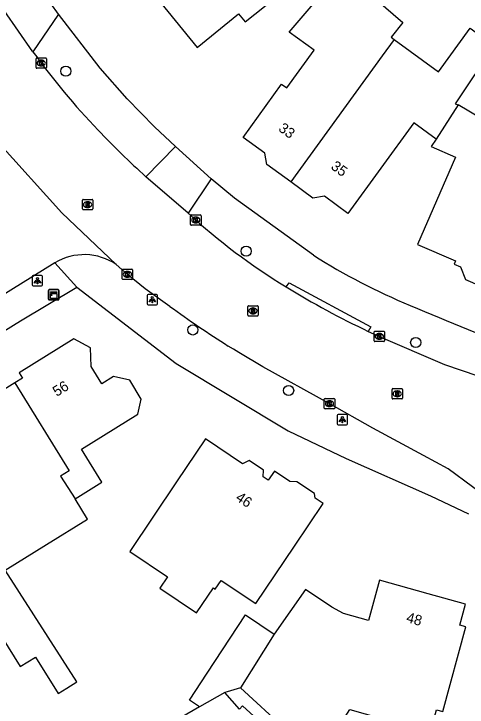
# Model space of a CAD drawing. Extents: x 161354 to 161876, y 382161 to 382804.
# Drawn here: x 161671.1 to 161714.8, y 382269.2 to 382336.2 of the extents above; entities that cross this region are included whole.
import ezdxf

# ---------------------------------------------------------------- set-up
doc = ezdxf.new("R2010")
doc.units = 0
for name, color, linetype in [('IMGEO_Boom', 7, 'Continuous'), ('IMGEO_Kast', 7, 'Continuous'), ('IMGEO_Kolk', 7, 'Continuous'), ('IMGEO_Lichtpunt', 7, 'Continuous'), ('IMGEO_Pand', 7, 'Continuous'), ('IMGEO_Pand_nummerreeks', 7, 'Continuous'), ('IMGEO_Rijbaan_lokaal_gesloten', 7, 'Continuous'), ('IMGEO_Rijbaan_lokaal_open', 7, 'Continuous'), ('IMGEO_Rioolput', 7, 'Continuous'), ('IMGEO_Voetpad_open', 7, 'Continuous')]:
    doc.layers.add(name, color=color, linetype=linetype)

msp = doc.modelspace()

# ---------------------------------------------------------------- linework, layer by layer
at = {"layer": 'IMGEO_Boom'}
for centre in [(161676.091, 382330.668), (161693.506, 382313.278), (161688.344, 382305.671), (161709.873, 382304.465), (161697.6, 382299.825)]:
    msp.add_circle(centre, 0.489, dxfattribs=at)
at = {"layer": 'IMGEO_Kast'}
for p, q in [((161674.412, 382308.644), (161674.412, 382309.485)), ((161674.412, 382309.485), (161674.412, 382308.644)), ((161674.487, 382309.569), (161675.328, 382309.569)), ((161675.328, 382309.569), (161674.487, 382309.569)), ((161675.412, 382309.494), (161675.412, 382308.653)), ((161675.412, 382308.653), (161675.412, 382309.494)), ((161675.337, 382308.569), (161674.496, 382308.569)), ((161674.496, 382308.569), (161675.337, 382308.569))]:
    msp.add_line(p, q, dxfattribs=at)
for points in [[(161674.607, 382309.359), (161675.207, 382309.359), (161675.207, 382309.274), (161674.607, 382309.274), (161674.607, 382309.359)], [(161674.607, 382309.184), (161675.207, 382309.184), (161675.207, 382308.695), (161674.607, 382308.695), (161674.607, 382309.184)]]:
    msp.add_lwpolyline(points, dxfattribs=at)
msp.add_circle((161674.691, 382309.033), 0.0377, dxfattribs=at)
for centre, start, end in [((161674.49, 382309.491), 92.4484, 184.28452), ((161674.49, 382309.491), 92.4484, 184.28452), ((161675.334, 382309.491), 2.4484, 94.28452), ((161675.334, 382309.491), 2.4484, 94.28452), ((161674.49, 382308.647), 182.4484, 274.28452), ((161674.49, 382308.647), 182.4484, 274.28452), ((161675.334, 382308.647), 272.4484, 4.28452), ((161675.334, 382308.647), 272.4484, 4.28452)]:
    msp.add_arc(centre, 0.0779, start, end, dxfattribs=at)
at = {"layer": 'IMGEO_Kolk'}
for p, q in [((161673.212, 382331.018), (161673.212, 382331.87)), ((161673.287, 382331.944), (161674.139, 382331.944)), ((161673.7, 382331.724), (161673.725, 382331.724)), ((161674.213, 382331.87), (161674.213, 382331.018)), ((161673.723, 382331.164), (161673.698, 382331.164)), ((161674.139, 382330.944), (161673.287, 382330.944)), ((161688.137, 382315.856), (161688.137, 382316.708)), ((161688.212, 382316.782), (161689.064, 382316.782)), ((161688.625, 382316.562), (161688.65, 382316.562)), ((161689.138, 382316.708), (161689.138, 382315.856)), ((161689.064, 382315.782), (161688.212, 382315.782)), ((161688.648, 382316.002), (161688.623, 382316.002)), ((161681.528, 382310.615), (161681.528, 382311.467)), ((161681.603, 382311.541), (161682.455, 382311.541)), ((161682.016, 382311.321), (161682.041, 382311.321)), ((161682.529, 382311.467), (161682.529, 382310.615)), ((161682.455, 382310.541), (161681.603, 382310.541)), ((161682.039, 382310.761), (161682.014, 382310.761)), ((161705.858, 382304.622), (161705.858, 382305.474)), ((161705.933, 382305.548), (161706.785, 382305.548)), ((161706.346, 382305.328), (161706.371, 382305.328)), ((161706.859, 382305.474), (161706.859, 382304.622)), ((161706.785, 382304.548), (161705.933, 382304.548)), ((161706.369, 382304.768), (161706.344, 382304.768)), ((161701.046, 382298.125), (161701.046, 382298.977)), ((161701.121, 382299.051), (161701.973, 382299.051)), ((161702.047, 382298.977), (161702.047, 382298.125)), ((161701.557, 382298.271), (161701.532, 382298.271)), ((161701.534, 382298.831), (161701.559, 382298.831)), ((161701.973, 382298.051), (161701.121, 382298.051))]:
    msp.add_line(p, q, dxfattribs=at)
for points in [[(161673.212, 382331.018), (161673.212, 382331.87)], [(161673.287, 382331.944), (161674.139, 382331.944)], [(161674.213, 382331.87), (161674.213, 382331.018)], [(161673.533, 382331.644), (161673.656, 382331.644), (161673.656, 382331.493), (161673.786, 382331.644), (161673.95, 382331.644), (161673.804, 382331.493), (161673.957, 382331.244), (161673.805, 382331.244), (161673.72, 382331.408), (161673.656, 382331.341), (161673.656, 382331.244), (161673.533, 382331.244), (161673.533, 382331.644)], [(161674.139, 382330.944), (161673.287, 382330.944)], [(161688.137, 382315.856), (161688.137, 382316.708)], [(161688.212, 382316.782), (161689.064, 382316.782)], [(161688.458, 382316.482), (161688.581, 382316.482), (161688.581, 382316.331), (161688.711, 382316.482), (161688.875, 382316.482), (161688.729, 382316.331), (161688.882, 382316.082), (161688.73, 382316.082), (161688.645, 382316.246), (161688.581, 382316.179), (161688.581, 382316.082), (161688.458, 382316.082), (161688.458, 382316.482)], [(161689.138, 382316.708), (161689.138, 382315.856)], [(161689.064, 382315.782), (161688.212, 382315.782)], [(161681.528, 382310.615), (161681.528, 382311.467)], [(161681.603, 382311.541), (161682.455, 382311.541)], [(161681.849, 382311.241), (161681.972, 382311.241), (161681.972, 382311.09), (161682.102, 382311.241), (161682.266, 382311.241), (161682.12, 382311.09), (161682.273, 382310.841), (161682.121, 382310.841), (161682.036, 382311.005), (161681.972, 382310.938), (161681.972, 382310.841), (161681.849, 382310.841), (161681.849, 382311.241)], [(161682.529, 382311.467), (161682.529, 382310.615)], [(161682.455, 382310.541), (161681.603, 382310.541)], [(161705.858, 382304.622), (161705.858, 382305.474)], [(161705.933, 382305.548), (161706.785, 382305.548)], [(161706.179, 382305.248), (161706.302, 382305.248), (161706.302, 382305.097), (161706.432, 382305.248), (161706.596, 382305.248), (161706.45, 382305.097), (161706.603, 382304.848), (161706.451, 382304.848), (161706.366, 382305.012), (161706.302, 382304.945), (161706.302, 382304.848), (161706.179, 382304.848), (161706.179, 382305.248)], [(161706.859, 382305.474), (161706.859, 382304.622)], [(161706.785, 382304.548), (161705.933, 382304.548)], [(161701.046, 382298.125), (161701.046, 382298.977)], [(161701.121, 382299.051), (161701.973, 382299.051)], [(161702.047, 382298.977), (161702.047, 382298.125)], [(161701.367, 382298.751), (161701.49, 382298.751), (161701.49, 382298.6), (161701.62, 382298.751), (161701.784, 382298.751), (161701.638, 382298.6), (161701.791, 382298.351), (161701.639, 382298.351), (161701.554, 382298.515), (161701.49, 382298.448), (161701.49, 382298.351), (161701.367, 382298.351), (161701.367, 382298.751)], [(161701.973, 382298.051), (161701.121, 382298.051)]]:
    msp.add_lwpolyline(points, dxfattribs=at)
for centre, start, end in [((161673.289, 382331.868), 91.55205, 178.44795), ((161673.289, 382331.868), 91.55205, 178.44795), ((161674.137, 382331.868), 1.55205, 88.44795), ((161674.137, 382331.868), 1.55205, 88.44795), ((161673.289, 382331.02), 181.55205, 268.44795), ((161673.289, 382331.02), 181.55205, 268.44795), ((161674.137, 382331.02), 271.55205, 358.44795), ((161674.137, 382331.02), 271.55205, 358.44795), ((161688.214, 382316.706), 91.55205, 178.44795), ((161688.214, 382316.706), 91.55205, 178.44795), ((161689.062, 382316.706), 1.55205, 88.44795), ((161689.062, 382316.706), 1.55205, 88.44795), ((161688.214, 382315.858), 181.55205, 268.44795), ((161688.214, 382315.858), 181.55205, 268.44795), ((161689.062, 382315.858), 271.55205, 358.44795), ((161689.062, 382315.858), 271.55205, 358.44795), ((161681.605, 382311.465), 91.55205, 178.44795), ((161681.605, 382311.465), 91.55205, 178.44795), ((161682.453, 382311.465), 1.55205, 88.44795), ((161682.453, 382311.465), 1.55205, 88.44795), ((161681.605, 382310.617), 181.55205, 268.44795), ((161681.605, 382310.617), 181.55205, 268.44795), ((161682.453, 382310.617), 271.55205, 358.44795), ((161682.453, 382310.617), 271.55205, 358.44795), ((161705.935, 382305.472), 91.55205, 178.44795), ((161705.935, 382305.472), 91.55205, 178.44795), ((161706.783, 382305.472), 1.55205, 88.44795), ((161706.783, 382305.472), 1.55205, 88.44795), ((161705.935, 382304.624), 181.55205, 268.44795), ((161705.935, 382304.624), 181.55205, 268.44795), ((161706.783, 382304.624), 271.55205, 358.44795), ((161706.783, 382304.624), 271.55205, 358.44795), ((161701.123, 382298.975), 91.55205, 178.44795), ((161701.123, 382298.975), 91.55205, 178.44795), ((161701.971, 382298.975), 1.55205, 88.44795), ((161701.971, 382298.975), 1.55205, 88.44795), ((161701.123, 382298.127), 181.55205, 268.44795), ((161701.123, 382298.127), 181.55205, 268.44795), ((161701.971, 382298.127), 271.55205, 358.44795), ((161701.971, 382298.127), 271.55205, 358.44795)]:
    msp.add_arc(centre, 0.0765, start, end, dxfattribs=at)
for centre, major_axis, ratio, start_param, end_param in [((161673.699, 382331.444), (-0.387, 0.002), 0.722429, 4.712389, 7.853982), ((161673.724, 382331.444), (-0.39, 0.002), 0.717154, 1.570796, 4.712389), ((161688.624, 382316.282), (-0.387, 0.002), 0.722429, 4.712389, 7.853982), ((161688.649, 382316.282), (-0.39, 0.002), 0.717154, 1.570796, 4.712389), ((161682.015, 382311.041), (-0.387, 0.002), 0.722429, 4.712389, 7.853982), ((161682.04, 382311.041), (-0.39, 0.002), 0.717154, 1.570796, 4.712389), ((161706.345, 382305.048), (-0.387, 0.002), 0.722429, 4.712389, 7.853982), ((161706.37, 382305.048), (-0.39, 0.002), 0.717154, 1.570796, 4.712389), ((161701.533, 382298.551), (-0.387, 0.002), 0.722429, 4.712389, 7.853982), ((161701.558, 382298.551), (-0.39, 0.002), 0.717154, 1.570796, 4.712389)]:
    msp.add_ellipse(centre, major_axis=major_axis, ratio=ratio, start_param=start_param, end_param=end_param, dxfattribs=at)
at = {"layer": 'IMGEO_Lichtpunt'}
for p, q in [((161672.845, 382310.83), (161672.845, 382310.023)), ((161672.845, 382310.83), (161672.845, 382310.023)), ((161673.747, 382310.925), (161672.939, 382310.925)), ((161673.747, 382310.925), (161672.939, 382310.925)), ((161673.841, 382310.023), (161673.841, 382310.83)), ((161673.841, 382310.023), (161673.841, 382310.83)), ((161672.939, 382309.929), (161673.747, 382309.929)), ((161672.939, 382309.929), (161673.747, 382309.929)), ((161683.932, 382309), (161683.932, 382308.193)), ((161683.932, 382309), (161683.932, 382308.193)), ((161684.834, 382309.095), (161684.026, 382309.095)), ((161684.834, 382309.095), (161684.026, 382309.095)), ((161684.928, 382308.193), (161684.928, 382309)), ((161684.928, 382308.193), (161684.928, 382309)), ((161684.026, 382308.099), (161684.834, 382308.099)), ((161684.026, 382308.099), (161684.834, 382308.099)), ((161702.292, 382297.423), (161702.292, 382296.616)), ((161702.292, 382297.423), (161702.292, 382296.616)), ((161703.194, 382297.518), (161702.386, 382297.518)), ((161703.194, 382297.518), (161702.386, 382297.518)), ((161703.288, 382296.616), (161703.288, 382297.423)), ((161703.288, 382296.616), (161703.288, 382297.423)), ((161702.386, 382296.522), (161703.194, 382296.522)), ((161702.386, 382296.522), (161703.194, 382296.522))]:
    msp.add_line(p, q, dxfattribs=at)
for points in [[(161673.219, 382310.494), (161673.258, 382310.466), (161673.07, 382310.204), (161673.032, 382310.231), (161673.219, 382310.494)], [(161673.321, 382310.446), (161673.368, 382310.446), (161673.368, 382310.124), (161673.321, 382310.124), (161673.321, 382310.446)], [(161673.431, 382310.466), (161673.469, 382310.493), (161673.656, 382310.231), (161673.617, 382310.203), (161673.431, 382310.466)], [(161684.306, 382308.664), (161684.345, 382308.636), (161684.157, 382308.374), (161684.119, 382308.401), (161684.306, 382308.664)], [(161684.408, 382308.616), (161684.455, 382308.616), (161684.455, 382308.294), (161684.408, 382308.294), (161684.408, 382308.616)], [(161684.518, 382308.636), (161684.556, 382308.663), (161684.743, 382308.401), (161684.704, 382308.373), (161684.518, 382308.636)], [(161702.666, 382297.087), (161702.705, 382297.059), (161702.517, 382296.797), (161702.479, 382296.824), (161702.666, 382297.087)], [(161702.768, 382297.039), (161702.815, 382297.039), (161702.815, 382296.717), (161702.768, 382296.717), (161702.768, 382297.039)], [(161702.878, 382297.059), (161702.916, 382297.086), (161703.103, 382296.824), (161703.064, 382296.796), (161702.878, 382297.059)]]:
    msp.add_lwpolyline(points, dxfattribs=at)
for centre in [(161673.344, 382310.628), (161684.431, 382308.798), (161702.791, 382297.221)]:
    msp.add_circle(centre, 0.0994, dxfattribs=at)
for centre, start, end in [((161672.939, 382310.83), 90, 180), ((161672.939, 382310.83), 90, 180), ((161673.747, 382310.83), 0, 90), ((161673.747, 382310.83), 0, 90), ((161672.939, 382310.023), 180, 270), ((161672.939, 382310.023), 180, 270), ((161673.747, 382310.023), 270, 0), ((161673.747, 382310.023), 270, 360), ((161684.026, 382309), 90, 180), ((161684.026, 382309), 90, 180), ((161684.834, 382309), 0, 90), ((161684.834, 382309), 0, 90), ((161684.026, 382308.193), 180, 270), ((161684.026, 382308.193), 180, 270), ((161684.834, 382308.193), 270, 0), ((161684.834, 382308.193), 270, 360), ((161702.386, 382297.423), 90, 180), ((161702.386, 382297.423), 90, 180), ((161703.194, 382297.423), 0, 90), ((161703.194, 382297.423), 0, 90), ((161702.386, 382296.616), 180, 270), ((161702.386, 382296.616), 180, 270), ((161703.194, 382296.616), 270, 0), ((161703.194, 382296.616), 270, 360)]:
    msp.add_arc(centre, 0.0946, start, end, dxfattribs=at)
at = {"layer": 'IMGEO_Pand'}
for points in [[(161689.288, 382352.192), (161691.267, 382349.342), (161682.503, 382342.228), (161683.854, 382340.562), (161683.091, 382339.943), (161688.753, 382332.965), (161692.759, 382336.218), (161693.41, 382335.415), (161697.292, 382338.567), (161696.655, 382339.476), (161700.969, 382343.026), (161700.325, 382343.81), (161700.84, 382344.233), (161698.7, 382346.834), (161698.203, 382346.426), (161697.822, 382346.113), (161694.352, 382350.333), (161697.755, 382353.161), (161694.67, 382356.587), (161689.288, 382352.192)], [(161697.801, 382319.966), (161695.49, 382321.644), (161695.317, 382322.735), (161693.197, 382324.274), (161696.924, 382329.406), (161697.426, 382329.042), (161700.071, 382332.684), (161697.644, 382334.447), (161701.127, 382338.509), (161702.784, 382340.442), (161708.643, 382335.359), (161707.512, 382333.942), (161707.794, 382333.736)], [(161707.794, 382333.736), (161712.072, 382330.605), (161715.133, 382334.815), (161717.458, 382333.145), (161713.667, 382327.503), (161713.965, 382327.4)], [(161707.794, 382333.736), (161706.639, 382332.144), (161697.801, 382319.966)], [(161711.832, 382324.112), (161711.351, 382323.387), (161713.706, 382322.37), (161710.058, 382313.92), (161713.718, 382312.34), (161713.582, 382312.025), (161714.196, 382311.76), (161714.676, 382310.552), (161716.09, 382309.942), (161717.306, 382310.425), (161717.973, 382310.137), (161718.11, 382310.453), (161720.912, 382309.243), (161722.74, 382313.478), (161723.843, 382316.818), (161724.233, 382317.722), (161718.202, 382320.324), (161718.445, 382320.992), (161718.691, 382321.669), (161719.748, 382324.574), (161716.614, 382325.927), (161716.201, 382326.105), (161713.965, 382327.4)], [(161713.965, 382327.4), (161711.832, 382324.112)], [(161711.832, 382324.112), (161709.68, 382325.673), (161703.327, 382316.927), (161701.051, 382318.58), (161699.95, 382318.406), (161697.801, 382319.966)], [(161676.982, 382289.356), (161679.576, 382290.958), (161677.589, 382294.173), (161683.024, 382297.53), (161683.372, 382299.001), (161682.252, 382300.815), (161680.7, 382301.182), (161679.556, 382300.475), (161678.52, 382302.152), (161678.466, 382303.955), (161676.863, 382304.819), (161671.563, 382301.546), (161671.893, 382301.012), (161671.167, 382300.564)], [(161671.167, 382300.564), (161667.693, 382298.419), (161667.357, 382298.964), (161665.731, 382298.729), (161664.633, 382297.242), (161670.122, 382288.352), (161667.515, 382286.765), (161668.811, 382284.635)], [(161671.167, 382300.564), (161676.401, 382292.075), (161675.569, 382291.551), (161676.982, 382289.356)], [(161694.442, 382279.26), (161698.152, 382284.776), (161700.94, 382288.926), (161700.176, 382289.439), (161700.093, 382289.862), (161698.393, 382291.004), (161697.714, 382291.051), (161696.229, 382292.048), (161695.625, 382291.149), (161695.128, 382291.483), (161695.173, 382292.137), (161693.789, 382293.067), (161693.131, 382292.745), (161689.556, 382295.147), (161686.768, 382290.997), (161682.251, 382284.274), (161685.904, 382281.821), (161685.168, 382280.725), (161688.714, 382278.344), (161690.337, 382280.76), (161690.514, 382280.641), (161691.078, 382281.48), (161694.442, 382279.26)], [(161670.232, 382282.483), (161674.21, 382284.94), (161678.191, 382287.399), (161676.982, 382289.356)], [(161669.948, 382275.971), (161671.683, 382273.162), (161673.158, 382274.073), (161675.33, 382270.557), (161676.175, 382271.079), (161677.138, 382271.674), (161670.232, 382282.483)], [(161692.941, 382271.118), (161697.309, 382267.116), (161700.449, 382264.239), (161703.511, 382269), (161706.473, 382268.194), (161711.296, 382266.878), (161711.873, 382268.992), (161712.484, 382268.825), (161714.716, 382277.009), (161714.125, 382277.17), (161714.678, 382279.199), (161711.071, 382280.2), (161706.387, 382281.505), (161705.326, 382277.613), (161702.901, 382278.274), (161701.774, 382278.908), (161699.217, 382280.602), (161696.218, 382276.307)], [(161689.004, 382269.269), (161688.018, 382269.917), (161689.722, 382272.511), (161693.421, 382278.144), (161696.218, 382276.307)], [(161696.218, 382276.307), (161692.941, 382271.118)], [(161692.941, 382271.118), (161691.677, 382270.72), (161691.439, 382270.645)], [(161691.439, 382270.645), (161689.004, 382269.269)], [(161698.253, 382264.695), (161693.147, 382269.374), (161692.845, 382269.044), (161691.439, 382270.645)], [(161689.004, 382269.269), (161687.169, 382268.226)]]:
    msp.add_lwpolyline(points, dxfattribs=at)
at = {"layer": 'IMGEO_Rijbaan_lokaal_gesloten'}
for points in [[(161672.905, 382332.54), (161670.126, 382336.516), (161666.872, 382341.08)], [(161669.454, 382323.886), (161675.695, 382316.977), (161680.957, 382311.996)], [(161687.884, 382316.957), (161683.812, 382320.469)], [(161686.143, 382307.952), (161683.751, 382309.654), (161682.033, 382311.039), (161680.957, 382311.996)], [(161705.294, 382305.538), (161705.79, 382305.306), (161706.287, 382305.077), (161712.666, 382302.344), (161720.606, 382299.646), (161721.129, 382299.474), (161726.271, 382297.814), (161743.873, 382292.487), (161745.606, 382291.947)], [(161717.698, 382288.771), (161713.02, 382292.272), (161710.614, 382293.536), (161705.719, 382296.186), (161701.507, 382298.575), (161695.116, 382302.112), (161692.781, 382303.491), (161692.274, 382303.804), (161691.768, 382304.12)]]:
    msp.add_lwpolyline(points, dxfattribs=at)
for centre, radius, start, end in [((161731.348, 382374.726), 72.078, 215.82309, 223.66451), ((161749.151, 382392.058), 96.923, 223.80989, 227.61345), ((161730.068, 382363.139), 62.548, 227.59071, 238.47044), ((161741.23, 382381.541), 84.071, 238.54442, 244.69401), ((161741.887, 382383.734), 94.076, 233.66248, 237.80865)]:
    msp.add_arc(centre, radius, start, end, dxfattribs=at)
at = {"layer": 'IMGEO_Rijbaan_lokaal_open'}
msp.add_lwpolyline([(161675.035, 382312.158), (161661.309, 382303.664), (161653.759, 382298.992), (161645.583, 382293.956), (161641.382, 382291.368), (161637.303, 382288.856), (161635.555, 382287.777)], dxfattribs=at)
msp.add_arc((161677.869, 382307.448), 5.497, 55.82763, 121.03843, dxfattribs=at)
at = {"layer": 'IMGEO_Rioolput'}
for p, q in [((161677.687, 382317.354), (161677.687, 382318.206)), ((161677.762, 382318.28), (161678.614, 382318.28)), ((161678.175, 382318.06), (161678.2, 382318.06)), ((161678.688, 382318.206), (161678.688, 382317.354)), ((161678.614, 382317.28), (161677.762, 382317.28)), ((161678.198, 382317.5), (161678.173, 382317.5)), ((161693.656, 382307.087), (161693.656, 382307.939)), ((161693.731, 382308.013), (161694.583, 382308.013)), ((161694.144, 382307.793), (161694.169, 382307.793)), ((161694.657, 382307.939), (161694.657, 382307.087)), ((161694.583, 382307.013), (161693.731, 382307.013)), ((161694.167, 382307.233), (161694.142, 382307.233)), ((161707.589, 382299.078), (161707.589, 382299.93)), ((161707.664, 382300.004), (161708.516, 382300.004)), ((161708.077, 382299.784), (161708.102, 382299.784)), ((161708.59, 382299.93), (161708.59, 382299.078)), ((161708.516, 382299.004), (161707.664, 382299.004)), ((161708.1, 382299.224), (161708.075, 382299.224))]:
    msp.add_line(p, q, dxfattribs=at)
for points in [[(161677.687, 382317.354), (161677.687, 382318.206)], [(161677.762, 382318.28), (161678.614, 382318.28)], [(161678.276, 382317.978), (161678.024, 382317.98), (161678.024, 382317.58)], [(161678.024, 382317.58), (161678.148, 382317.58), (161678.148, 382317.742), (161678.159, 382317.742)], [(161678.202, 382317.899), (161678.148, 382317.899), (161678.148, 382317.818)], [(161678.148, 382317.818), (161678.2, 382317.818)], [(161678.206, 382317.713), (161678.277, 382317.58), (161678.417, 382317.58), (161678.352, 382317.706)], [(161678.688, 382318.206), (161678.688, 382317.354)], [(161678.614, 382317.28), (161677.762, 382317.28)], [(161693.656, 382307.087), (161693.656, 382307.939)], [(161693.731, 382308.013), (161694.583, 382308.013)], [(161694.245, 382307.711), (161693.993, 382307.713), (161693.993, 382307.313)], [(161694.171, 382307.632), (161694.117, 382307.632), (161694.117, 382307.551)], [(161694.657, 382307.939), (161694.657, 382307.087)], [(161694.583, 382307.013), (161693.731, 382307.013)], [(161693.993, 382307.313), (161694.117, 382307.313), (161694.117, 382307.475), (161694.128, 382307.475)], [(161694.117, 382307.551), (161694.169, 382307.551)], [(161694.175, 382307.446), (161694.246, 382307.313), (161694.386, 382307.313), (161694.321, 382307.439)], [(161707.589, 382299.078), (161707.589, 382299.93)], [(161707.664, 382300.004), (161708.516, 382300.004)], [(161708.178, 382299.702), (161707.926, 382299.704), (161707.926, 382299.304)], [(161708.104, 382299.623), (161708.05, 382299.623), (161708.05, 382299.542)], [(161708.59, 382299.93), (161708.59, 382299.078)], [(161708.516, 382299.004), (161707.664, 382299.004)], [(161707.926, 382299.304), (161708.05, 382299.304), (161708.05, 382299.466), (161708.061, 382299.466)], [(161708.05, 382299.542), (161708.102, 382299.542)], [(161708.108, 382299.437), (161708.179, 382299.304), (161708.319, 382299.304), (161708.254, 382299.43)]]:
    msp.add_lwpolyline(points, dxfattribs=at)
for centre, radius, start, end in [((161677.764, 382318.204), 0.0765, 91.55205, 178.44795), ((161677.764, 382318.204), 0.0765, 91.55205, 178.44795), ((161678.158, 382317.689), 0.0533, 26.02933, 88.69889), ((161678.184, 382318.007), 0.19, 274.7715, 282.96867), ((161678.208, 382317.803), 0.0964, 77.00612, 93.18647), ((161678.222, 382317.86), 0.0378, 276.66336, 79.67722), ((161678.275, 382317.868), 0.109, 350.36119, 89.41601), ((161678.273, 382317.868), 0.112, 277.58423, 350.98172), ((161678.257, 382317.653), 0.108, 29.51342, 73.79051), ((161678.612, 382318.204), 0.0765, 1.55205, 88.44795), ((161678.612, 382318.204), 0.0765, 1.55205, 88.44795), ((161677.764, 382317.356), 0.0765, 181.55205, 268.44795), ((161677.764, 382317.356), 0.0765, 181.55205, 268.44795), ((161678.612, 382317.356), 0.0765, 271.55205, 358.44795), ((161678.612, 382317.356), 0.0765, 271.55205, 358.44795), ((161693.733, 382307.937), 0.0765, 91.55205, 178.44795), ((161693.733, 382307.937), 0.0765, 91.55205, 178.44795), ((161694.177, 382307.536), 0.0964, 77.00612, 93.18647), ((161694.191, 382307.593), 0.0378, 276.66336, 79.67722), ((161694.244, 382307.601), 0.109, 350.36119, 89.41601), ((161694.581, 382307.937), 0.0765, 1.55205, 88.44795), ((161694.581, 382307.937), 0.0765, 1.55205, 88.44795), ((161693.733, 382307.089), 0.0765, 181.55205, 268.44795), ((161693.733, 382307.089), 0.0765, 181.55205, 268.44795), ((161694.127, 382307.422), 0.0533, 26.02933, 88.69889), ((161694.153, 382307.74), 0.19, 274.7715, 282.96867), ((161694.242, 382307.601), 0.112, 277.58423, 350.98172), ((161694.226, 382307.386), 0.108, 29.51342, 73.79051), ((161694.581, 382307.089), 0.0765, 271.55205, 358.44795), ((161694.581, 382307.089), 0.0765, 271.55205, 358.44795), ((161707.666, 382299.928), 0.0765, 91.55205, 178.44795), ((161707.666, 382299.928), 0.0765, 91.55205, 178.44795), ((161708.11, 382299.527), 0.0964, 77.00612, 93.18647), ((161708.124, 382299.584), 0.0378, 276.66336, 79.67722), ((161708.177, 382299.592), 0.109, 350.36119, 89.41601), ((161708.514, 382299.928), 0.0765, 1.55205, 88.44795), ((161708.514, 382299.928), 0.0765, 1.55205, 88.44795), ((161707.666, 382299.08), 0.0765, 181.55205, 268.44795), ((161707.666, 382299.08), 0.0765, 181.55205, 268.44795), ((161708.06, 382299.413), 0.0533, 26.02933, 88.69889), ((161708.086, 382299.731), 0.19, 274.7715, 282.96867), ((161708.175, 382299.592), 0.112, 277.58423, 350.98172), ((161708.159, 382299.377), 0.108, 29.51342, 73.79051), ((161708.514, 382299.08), 0.0765, 271.55205, 358.44795), ((161708.514, 382299.08), 0.0765, 271.55205, 358.44795)]:
    msp.add_arc(centre, radius, start, end, dxfattribs=at)
for centre, major_axis, ratio, start_param, end_param in [((161678.174, 382317.78), (-0.387, 0.002), 0.722429, 4.712389, 7.853982), ((161678.199, 382317.78), (-0.39, 0.002), 0.717154, 1.570796, 4.712389), ((161694.143, 382307.513), (-0.387, 0.002), 0.722429, 4.712389, 7.853982), ((161694.168, 382307.513), (-0.39, 0.002), 0.717154, 1.570796, 4.712389), ((161708.076, 382299.504), (-0.387, 0.002), 0.722429, 4.712389, 7.853982), ((161708.101, 382299.504), (-0.39, 0.002), 0.717154, 1.570796, 4.712389)]:
    msp.add_ellipse(centre, major_axis=major_axis, ratio=ratio, start_param=start_param, end_param=end_param, dxfattribs=at)
at = {"layer": 'IMGEO_Voetpad_open'}
for points in [[(161675.39, 382336.184), (161673.167, 382339.282), (161670.894, 382342.449)], [(161675.39, 382336.184), (161672.905, 382332.54)], [(161686.686, 382323.399), (161684.638, 382325.276), (161682.004, 382327.993), (161679.413, 382330.953), (161675.39, 382336.184)], [(161683.812, 382320.469), (161686.686, 382323.399)], [(161686.686, 382323.399), (161690.118, 382320.254)], [(161690.118, 382320.254), (161687.884, 382316.957)], [(161699.996, 382312.879), (161692.374, 382318.403), (161690.118, 382320.254)], [(161675.035, 382312.158), (161677.151, 382309.804)], [(161622.353, 382275.985), (161671.693, 382306.549), (161677.151, 382309.804)], [(161677.151, 382309.804), (161686.732, 382302.424), (161697.545, 382295.944), (161703.155, 382293.259), (161711.315, 382289.649), (161714.958, 382287.913)], [(161697.359, 382309.825), (161697.657, 382310.227), (161705.53, 382305.978), (161705.294, 382305.538)]]:
    msp.add_lwpolyline(points, dxfattribs=at)
for centre, radius, start, end in [((161733.455, 382365.976), 62.76, 237.78285, 247.39627), ((161823.77, 382576.859), 292.166, 246.94072, 249.31777)]:
    msp.add_arc(centre, radius, start, end, dxfattribs=at)

# ---------------------------------------------------------------- texts
at = {"layer": 'IMGEO_Pand_nummerreeks'}
for s, rotation, p in [('33', 324.0469, (161696.54, 382324.963)), ('35', 324.0469, (161701.605, 382321.289)), ('56', 31.69039, (161675.204, 382299.2)), ('46', 326.10332, (161692.402, 382289.283)), ('48', 344.74605, (161708.893, 382277.468))]:
    msp.add_text(s, height=1, rotation=rotation, dxfattribs=at).set_placement(p)

doc.saveas('drawing.dxf')
